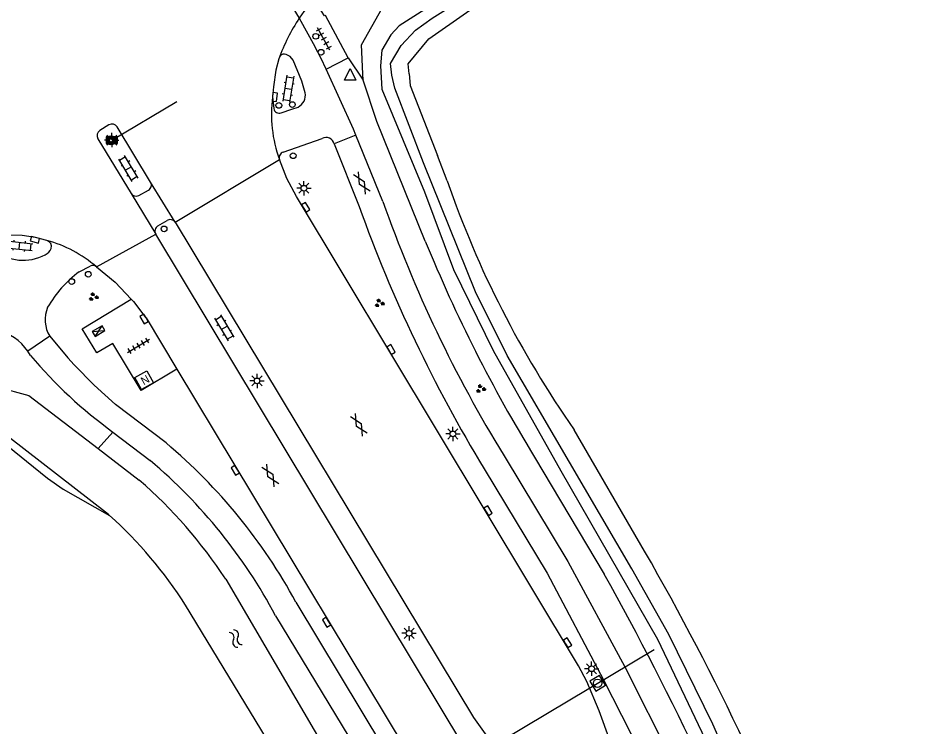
# Model space of a CAD drawing. Extents: x 133000 to 136000, y 400500 to 403500.
# Drawn here: x 133580.3 to 133659.3, y 400942.9 to 401004.9 of the extents above; entities that cross this region are included whole.
import ezdxf

# ---------------------------------------------------------------- set-up
doc = ezdxf.new("R2010")
doc.units = 0
for name, color, linetype in [('gg-afsc-erfafscheiding', 7, 'Continuous'), ('gg-knt-verharding', 7, 'Continuous'), ('gg-knt-verharding nz', 7, 'Continuous'), ('gg-kntw-bovenkant insteek waterloop', 7, 'Continuous'), ('gg-kntw-waterlijn', 7, 'Continuous'), ('gg-kwrk-duiker nz buis', 7, 'Continuous'), ('gt-grn-groengrens', 7, 'Continuous'), ('gt-grn-weggrens', 7, 'Continuous'), ('gt-knt-lijn portaal', 7, 'Continuous'), ('gt-symb-drukknoppaal', 7, 'Continuous'), ('gt-symb-gesloten verharding', 7, 'Continuous'), ('gt-symb-groenvak', 7, 'Continuous'), ('gt-symb-klinker verharding', 7, 'Continuous'), ('gt-symb-kolk', 7, 'Continuous'), ('gt-symb-lichtmast', 7, 'Continuous'), ('gt-symb-nortonput', 7, 'Continuous'), ('gt-symb-portaalmast', 7, 'Continuous'), ('gt-symb-rioolschacht', 7, 'Continuous'), ('gt-symb-tegel verharding', 7, 'Continuous'), ('gt-symb-verkeersregelinstallatiekast', 7, 'Continuous'), ('gt-symb-verkeersregelinstallatiepaal', 7, 'Continuous'), ('gt-symb-waterafsluiter', 7, 'Continuous'), ('gt-symb-watersymbool', 7, 'Continuous'), ('gt-symb-wegwijzer', 7, 'Continuous')]:
    doc.layers.add(name, color=color, linetype=linetype)

# ---------------------------------------------------------------- blocks, each defined once
blk = doc.blocks.new('gt0-LMAST')
at = {"layer": 'gt-symb-lichtmast'}
for p, q in [((-0.182, 0.173), (-0.447, 0.438)), ((-0.005, 0.246), (-0.005, 0.621)), ((0.172, 0.173), (0.437, 0.438)), ((-0.255, -0.004), (-0.63, -0.004)), ((-0.182, -0.181), (-0.447, -0.446)), ((-0.005, -0.254), (-0.005, -0.629)), ((0.437, -0.446), (0.172, -0.181)), ((0.245, -0.004), (0.62, -0.004))]:
    blk.add_line(p, q, dxfattribs=at)
blk.add_circle((-0.005, -0.004), 0.25, dxfattribs=at)
blk = doc.blocks.new('gt0-VIPAAL')
at = {"layer": 'gt-symb-verkeersregelinstallatiepaal'}
blk.add_circle((0, 0), 0.25, dxfattribs=at)
blk = doc.blocks.new('gt0-DPAAL')
at = {"layer": 'gt-symb-drukknoppaal'}
blk.add_circle((0, 0), 0.25, dxfattribs=at)
blk = doc.blocks.new('gt0-KOLK')
at = {"layer": 'gt-symb-kolk'}
blk.add_lwpolyline([(0, 0), (0.375, 0), (0.375, 0.4), (-0.375, 0.4), (-0.375, 0), (0, 0)], dxfattribs=at)
blk = doc.blocks.new('gt0-KL1')
at = {"layer": 'gt-symb-klinker verharding'}
for p, q in [((-1.15, 0.3), (1.15, 0.3)), ((-1, -0.3), (-1, 0.3)), ((-0.5, 0.3), (-0.5, 0.45)), ((0, -0.3), (0, 0.3)), ((0.5, 0.3), (0.5, 0.45)), ((1, -0.3), (1, 0.3)), ((-1.15, -0.3), (1.15, -0.3)), ((-0.5, -0.45), (-0.5, -0.3)), ((0.5, -0.45), (0.5, -0.3))]:
    blk.add_line(p, q, dxfattribs=at)
blk = doc.blocks.new('gt0-TEG1')
at = {"layer": 'gt-symb-tegel verharding'}
for p, q in [((-1.125, 0), (1.125, 0)), ((-0.9, -0.25), (-0.9, 0.25)), ((-0.45, -0.25), (-0.45, 0.25)), ((0, -0.25), (0, 0.25)), ((0.45, -0.25), (0.45, 0.25)), ((0.9, -0.25), (0.9, 0.25))]:
    blk.add_line(p, q, dxfattribs=at)
blk = doc.blocks.new('gt0-PORTM')
at = {"layer": 'gt-symb-portaalmast'}
for radius in [0.4, 0.33, 0.27, 0.21, 0.15]:
    blk.add_circle((0, 0), radius, dxfattribs=at)
blk = doc.blocks.new('gt0-WW')
at = {"layer": 'gt-symb-wegwijzer'}
blk.add_lwpolyline([(-0.5, 0.295), (-0.5, -0.295), (0.5, -0.295), (0.5, 0.295), (-0.5, 0.295)], dxfattribs=at)
blk.add_lwpolyline([(-0.418, -0.212), (0.417, -0.212), (0.417, 0.212), (-0.418, 0.212)], close=True, dxfattribs=at)
blk = doc.blocks.new('gt0-GRVAK')
at = {"layer": 'gt-symb-groenvak'}
for p, q in [((-0.11, 0.189), (-0.228, 0.24)), ((-0.182, 0.153), (0.088, 0.153)), ((-0.091, 0.211), (-0.156, 0.322)), ((-0.047, 0.214), (-0.047, 0.393)), ((-0.004, 0.211), (0.061, 0.322)), ((0.015, 0.189), (0.133, 0.24)), ((0.262, -0.052), (0.197, 0.059)), ((0.305, -0.049), (0.305, 0.13)), ((0.349, -0.052), (0.414, 0.059)), ((-0.245, -0.228), (-0.363, -0.177)), ((-0.318, -0.264), (-0.047, -0.264)), ((-0.226, -0.206), (-0.291, -0.095)), ((-0.183, -0.203), (-0.183, -0.024)), ((-0.139, -0.206), (-0.074, -0.095)), ((-0.12, -0.228), (-0.002, -0.177)), ((0.243, -0.074), (0.125, -0.023)), ((0.17, -0.11), (0.441, -0.11)), ((0.368, -0.074), (0.486, -0.023))]:
    blk.add_line(p, q, dxfattribs=at)
blk = doc.blocks.new('gt0-VRIKST')
at = {"layer": 'gt-symb-verkeersregelinstallatiekast'}
for p, q in [((-0.501, -0.249), (0.501, 0.249)), ((-0.501, 0.249), (0.501, -0.249))]:
    blk.add_line(p, q, dxfattribs=at)
blk.add_lwpolyline([(0.501, 0.249), (-0.501, 0.249), (-0.501, -0.249), (0.501, -0.249)], close=True, dxfattribs=at)
blk = doc.blocks.new('gt0-NPUT')
at = {"layer": 'gt-symb-nortonput'}
blk.add_lwpolyline([(-0.566, -0.608), (-0.566, 0.592), (0.634, 0.592), (0.634, -0.608)], close=True, dxfattribs=at)
blk.add_text('N', height=0.7, dxfattribs=at).set_placement((-0.221, -0.381))
blk = doc.blocks.new('gt0-WA')
at = {"layer": 'gt-symb-watersymbool'}
for centre, start, end in [((-0.323, 0.022), 28.07249, 151.92751), ((0.427, 0.422), 208.07248, 331.92751), ((-0.323, -0.428), 28.07249, 151.92751), ((0.427, -0.028), 208.07248, 331.92751)]:
    blk.add_arc(centre, 0.425, start, end, dxfattribs=at)
blk = doc.blocks.new('gt0-GESVH1')
at = {"layer": 'gt-symb-gesloten verharding'}
for p, q in [((-0.992, -0.261), (0.008, 0.239)), ((0.008, -0.261), (-0.992, 0.239)), ((0.008, 0.239), (1.008, -0.261)), ((1.008, 0.239), (0.008, -0.261))]:
    blk.add_line(p, q, dxfattribs=at)
blk = doc.blocks.new('gt0-WAFSL')
at = {"layer": 'gt-symb-waterafsluiter'}
for p, q in [((-0.5, -0.333), (0, 0.667)), ((0, 0.667), (0.5, -0.333)), ((0.5, -0.333), (-0.5, -0.333))]:
    blk.add_line(p, q, dxfattribs=at)
blk = doc.blocks.new('gt0-RS')
at = {"layer": 'gt-symb-rioolschacht'}
blk.add_lwpolyline([(-0.5, -0.5), (0.5, -0.5), (0.5, 0.5), (-0.5, 0.5)], close=True, dxfattribs=at)
blk.add_circle((0, 0), 0.375, dxfattribs=at)

msp = doc.modelspace()

# ---------------------------------------------------------------- linework, layer by layer
at = {"layer": 'gg-afsc-erfafscheiding'}
msp.add_lwpolyline([(133429.627, 400949.865), (133442.716, 400946.867), (133458.33, 400944.553), (133473.772, 400943.808), (133489.111, 400944.33), (133504.61, 400946.174), (133524.569, 400949.018), (133536.245, 400951.941), (133555.852, 400958.891), (133578.738, 400967.971), (133582.861, 400964.612), (133584.248, 400963.669), (133588.295, 400961.359)], dxfattribs=at)
at = {"layer": 'gg-knt-verharding'}
for p, q in [((133604.882, 401004.877), (133606.25, 401002.402)), ((133603.217, 401001.565), (133603.102, 401001.303)), ((133607.223, 401000.406), (133609.169, 401001.412)), ((133602.539, 400997.986), (133602.652, 400996.955)), ((133588.238, 400995.529), (133587.436, 400995.054)), ((133591.883, 400990.527), (133588.965, 400995.361)), ((133587.28, 400994.311), (133590.173, 400989.538)), ((133603.473, 400993.158), (133606.884, 400994.336)), ((133612.188, 400988.84), (133609.842, 400994.646)), ((133607.933, 400993.875), (133610.119, 400988.402)), ((133594.022, 400987.01), (133591.883, 400990.527)), ((133590.173, 400989.538), (133592.326, 400985.96)), ((133590.842, 400989.359), (133591.696, 400989.831)), ((133592.514, 400986.687), (133593.341, 400987.178)), ((133622.394, 400936.022), (133592.326, 400985.96)), ((133585.633, 400982.685), (133586.604, 400983.173)), ((133583.06, 400977.033), (133584.638, 400975.161)), ((133581.38, 400975.36), (133581.154, 400975.727)), ((133584.638, 400975.161), (133585.193, 400974.537)), ((133594.178, 400974.168), (133616.436, 400937.165)), ((133588.594, 400968.657), (133591.851, 400966.157)), ((133604.587, 400953.771), (133615.624, 400935.444)), ((133602.814, 400952.587), (133614.646, 400933.075))]:
    msp.add_line(p, q, dxfattribs=at)
for points in [[(133609.169, 401001.412), (133607.179, 401005.103), (133607.074, 401005.081), (133606.552, 401005.903)], [(133607.223, 401000.406), (133606.79, 401001.35), (133606.25, 401002.402)], [(133605.397, 400998.34), (133605.108, 400999.345), (133604.358, 401001.194), (133604.086, 401001.515), (133603.739, 401001.684)], [(133603.102, 401001.303), (133602.843, 401000.327), (133602.636, 400998.86), (133602.539, 400997.986)], [(133609.842, 400994.646), (133609.635, 400995.16), (133607.223, 401000.406)], [(133603.294, 400996.59), (133604.224, 400996.92), (133604.772, 400997.093)], [(133643.238, 400920.543), (133642.873, 400920.331), (133636.597, 400931.123), (133635.215, 400933.677), (133633.976, 400936.304), (133631.096, 400944.275), (133630.018, 400946.839), (133629.31, 400948.2), (133604.634, 400989.261), (133603.808, 400990.837), (133603.152, 400992.491), (133603.149, 400992.499)], [(133594.022, 400987.01), (133620.102, 400943.681), (133621.853, 400941.232)], [(133582.822, 400985.414), (133581.818, 400985.676), (133580.66, 400985.86), (133578.281, 400985.886), (133578.197, 400985.87)], [(133587.144, 400983.115), (133588.781, 400981.783), (133590.193, 400980.298)], [(133594.178, 400974.168), (133591.044, 400972.291), (133588.57, 400976.398), (133587.173, 400975.575), (133585.888, 400977.695), (133590.193, 400980.298)], [(133590.193, 400980.298), (133590.39, 400980.09), (133591.473, 400978.665)], [(133591.473, 400978.665), (133591.481, 400978.652), (133594.178, 400974.168)], [(133593.234, 400967.706), (133588.822, 400971.077), (133586.954, 400972.751), (133585.193, 400974.537)], [(133622.79, 400966.584), (133628.373, 400957.346), (133633.342, 400948.107), (133637.408, 400940.058), (133642.118, 400929.726), (133645.163, 400921.96)], [(133621.061, 400965.43), (133626.564, 400956.32), (133631.485, 400946.992), (133635.443, 400939.199), (133640.107, 400929.009), (133643.445, 400920.663), (133643.238, 400920.543)]]:
    msp.add_lwpolyline(points, dxfattribs=at)
for centre, radius, start, end in [((133618.529, 400995.84), 16.368, 136.91089, 146.48973), ((133618.494, 400995.867), 16.324, 146.50012, 160.54947), ((133603.562, 401001.254), 0.465, 67.65587, 138.02856), ((133604.297, 400998.111), 1.124, 295.01647, 11.74321), ((133614.053, 400996.489), 11.611, 172.59066, 200.0966), ((133603.114, 400997.021), 0.467, 188.08266, 292.67778), ((133588.515, 400995.071), 0.536, 32.83907, 121.13717), ((133587.737, 400994.603), 0.542, 123.71307, 212.5718), ((133607.234, 400993.708), 0.719, 13.45108, 119.10119), ((133603.632, 400992.671), 0.512, 108.04994, 199.58761), ((133591.455, 400990.269), 0.5, 298.80536, 31.11672), ((133590.601, 400989.798), 0.501, 211.24704, 298.79419), ((133721.638, 401027.325), 116.018, 199.37277, 211.5703), ((133728.656, 401030.771), 125.882, 199.66875, 211.26994), ((133593.596, 400986.747), 0.5, 31.64774, 120.63639), ((133592.778, 400986.231), 0.527, 120.10338, 210.89883), ((133582.658, 400984.883), 0.556, 342.87606, 72.79721), ((133580.731, 400987.799), 4.11, 231.28374, 298.03141), ((133582.179, 400985.163), 1.103, 295.95387, 336.28438), ((133592.07, 400974.214), 10.639, 127.2324, 149.76831), ((133585.522, 400978.485), 2.858, 157.67321, 210.53011), ((133577.43, 400973.173), 4.515, 34.43853, 118.11645), ((133612.682, 401001.815), 40.984, 220.20285, 234.0028), ((133562.317, 400930.926), 48.048, 28.38977, 49.95041), ((133562.318, 400931.085), 45.85, 27.96746, 49.90099)]:
    msp.add_arc(centre, radius, start, end, dxfattribs=at)
at = {"layer": 'gg-knt-verharding nz'}
for centre, radius, start, end in [((133579.943, 400974.79), 11.007, 49.14108, 74.83925), ((133586.829, 400982.727), 0.499, 50.9258, 116.81322)]:
    msp.add_arc(centre, radius, start, end, dxfattribs=at)
at = {"layer": 'gg-kntw-bovenkant insteek waterloop'}
for p, q in [((133610.48, 400999.43), (133610.454, 401000)), ((133617.826, 400990.628), (133616.964, 400992.854)), ((133635.078, 400958.233), (133628.929, 400968.862)), ((133587.308, 400967.207), (133590.884, 400964.463)), ((133625.459, 400966.466), (133631.548, 400956.23)), ((133598.45, 400955.778), (133611.212, 400934.007)), ((133607.901, 400932.143), (133594.931, 400953.522))]:
    msp.add_line(p, q, dxfattribs=at)
for points in [[(133610.454, 401000), (133610.337, 401002.541), (133612.12, 401005.733), (133633.867, 401018.749), (133649.14, 401028.319), (133655.678, 401032.336), (133664.278, 401037.462), (133672.933, 401042.494), (133680.547, 401046.788), (133688.225, 401050.968), (133697.299, 401055.725), (133706.431, 401060.369), (133707.975, 401061.051), (133711.698, 401062.516), (133713.355, 401059.623)], [(133614.492, 401000), (133614.416, 401000.87), (133616.202, 401003.055), (133623.098, 401007.897), (133635.496, 401015.813), (133639.764, 401018.462), (133648.605, 401023.858), (133657.482, 401029.194), (133666.111, 401034.245), (133673.135, 401038.207)], [(133614.492, 401000), (133614.583, 400998.968), (133616.964, 400992.854)], [(133588.295, 400961.359), (133588.192, 400961.451), (133579.361, 400968.304), (133578.58, 400968.502), (133571.943, 400966.804), (133565.509, 400965.052), (133559.077, 400962.776), (133539.963, 400956.262), (133519.917, 400950.936), (133499.845, 400947.79), (133478.527, 400946.659), (133457.666, 400947.654), (133436.605, 400950.84), (133415.789, 400956.042), (133374.475, 400971.814), (133356.681, 400978.499), (133345.411, 400982.38), (133332.882, 400986.151), (133319.753, 400989.747), (133303.119, 400993.146), (133285.229, 400995.886), (133269.888, 400998.388), (133256.467, 400999.27)], [(133615.901, 400985.371), (133611.658, 400995.839), (133610.48, 400999.43)], [(133557.489, 400966.438), (133558.125, 400966.65), (133564.041, 400968.841), (133570.425, 400970.617), (133578.451, 400972.606), (133581.25, 400971.856), (133587.308, 400967.207)]]:
    msp.add_lwpolyline(points, dxfattribs=at)
for centre, radius, start, end in [((133700.133, 401018.899), 87.027, 198.95642, 215.09652), ((133734.998, 401033.715), 128.535, 202.09345, 211.54709), ((133563.396, 400932.879), 41.871, 33.15504, 48.96693), ((133563.193, 400933.376), 37.593, 32.40607, 48.10662), ((133441.615, 400846.777), 223.272, 20.24389, 29.94663), ((133406.374, 400830.346), 257.973, 20.93223, 29.20755)]:
    msp.add_arc(centre, radius, start, end, dxfattribs=at)
at = {"layer": 'gg-kntw-waterlijn'}
for points in [[(133669.178, 400882.869), (133660.123, 400899.947), (133656.816, 400906.406), (133654.565, 400911.047), (133649.821, 400922.128), (133646.196, 400931.346), (133641.046, 400943.094), (133637.201, 400950.933), (133633.964, 400956.689), (133623.055, 400975.355), (133620.284, 400980.931), (133615.747, 400992.22), (133613.24, 400998.75), (133612.979, 400999.877), (133612.868, 401000.913), (133613.799, 401002.477), (133615.033, 401003.815), (133616.515, 401004.871), (133629.865, 401013.235), (133660.984, 401032.244), (133689.357, 401048.211), (133697.388, 401052.73), (133707.228, 401057.72)], [(133702.993, 401056.634), (133698.278, 401054.31), (133668.171, 401037.676), (133654.636, 401029.646), (133630.286, 401014.659), (133622.458, 401009.841), (133613.627, 401004.192), (133612.898, 401003.401), (133612.106, 401002.064), (133611.983, 401000.708), (133612.106, 400998.666), (133615.821, 400989.679), (133618.371, 400982.882), (133621.825, 400975.783), (133627.738, 400965.269), (133636.197, 400950.536), (133640.667, 400941.171), (133648.674, 400922.773), (133653.89, 400910.159), (133663.361, 400891.527), (133670.025, 400879.232)]]:
    msp.add_lwpolyline(points, dxfattribs=at)
at = {"layer": 'gg-kwrk-duiker nz buis'}
msp.add_lwpolyline([(133609.989, 400934.441), (133615.169, 400937.241), (133635.906, 400949.645)], dxfattribs=at)
at = {"layer": 'gt-grn-groengrens'}
for p, q in [((133609.169, 401001.412), (133610.48, 400999.43)), ((133587.308, 400967.207), (133588.594, 400968.657))]:
    msp.add_line(p, q, dxfattribs=at)
at = {"layer": 'gt-grn-weggrens'}
for p, q in [((133600.26, 401012.404), (133604.882, 401004.877)), ((133609.842, 400994.646), (133607.933, 400993.875)), ((133594.022, 400987.01), (133603.149, 400992.499)), ((133587.144, 400983.115), (133592.326, 400985.96)), ((133583.06, 400977.033), (133581.154, 400975.727))]:
    msp.add_line(p, q, dxfattribs=at)
at = {"layer": 'gt-knt-lijn portaal'}
msp.add_line((133588.495, 400994.203), (133594.168, 400997.577), dxfattribs=at)

# ---------------------------------------------------------------- block references
at = {"layer": 'gt-symb-drukknoppaal'}
for p in [(133606.786, 401001.888), (133604.275, 400997.309), (133584.985, 400981.823)]:
    msp.add_blockref('gt0-DPAAL', p, dxfattribs=at)
at = {"layer": 'gt-symb-gesloten verharding'}
for p, rotation in [((133610.355, 400990.465), -58.996932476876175), ((133610.086, 400969.269), 121.05216071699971), ((133602.347, 400964.846), 121.05216071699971)]:
    msp.add_blockref('gt0-GESVH1', p, dxfattribs=dict(at, rotation=rotation))
at = {"layer": 'gt-symb-groenvak'}
for p in [(133586.883, 400980.488), (133611.882, 400979.932), (133620.738, 400972.442)]:
    msp.add_blockref('gt0-GRVAK', p, dxfattribs=at)
at = {"layer": 'gt-symb-klinker verharding'}
for p, rotation in [((133603.918, 400998.703), -99.20796905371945), ((133589.946, 400991.712), 121.05216071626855), ((133580.409, 400984.959), -6.143995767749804), ((133598.318, 400977.782), -58.99693247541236)]:
    msp.add_blockref('gt0-KL1', p, dxfattribs=dict(at, rotation=rotation))
at = {"layer": 'gt-symb-kolk'}
for p, rotation in [((133602.539, 400997.986), -96.31488442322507), ((133605.279, 400988.223), -58.12218352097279), ((133581.818, 400985.676), 165.35262473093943), ((133591.481, 400978.652), 121.05216071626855), ((133612.728, 400975.777), -59.075540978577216), ((133599.451, 400965.415), 121.00306752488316), ((133621.223, 400961.677), -58.94783928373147), ((133607.44, 400952.128), 121.00306752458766), ((133628.168, 400950.125), -58.996932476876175)]:
    msp.add_blockref('gt0-KOLK', p, dxfattribs=dict(at, rotation=rotation))
at = {"layer": 'gt-symb-lichtmast'}
for p in [(133588.495, 400994.203), (133605.291, 400989.99), (133601.192, 400973.14), (133618.317, 400968.496), (133614.488, 400951.054), (133630.446, 400947.955)]:
    msp.add_blockref('gt0-LMAST', p, dxfattribs=at)
at = {"layer": 'gt-symb-nortonput', "rotation": 29.588607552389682}
msp.add_blockref('gt0-NPUT', (133591.285, 400973.183), dxfattribs=at)
at = {"layer": 'gt-symb-portaalmast'}
msp.add_blockref('gt0-PORTM', (133588.418, 400994.174), dxfattribs=at)
at = {"layer": 'gt-symb-rioolschacht', "rotation": 30.79671391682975}
msp.add_blockref('gt0-RS', (133630.972, 400946.678), dxfattribs=at)
at = {"layer": 'gt-symb-tegel verharding'}
for p, rotation in [((133607.016, 401003.055), 119.28282857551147), ((133590.832, 400976.207), 31.13079914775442)]:
    msp.add_blockref('gt0-TEG1', p, dxfattribs=dict(at, rotation=rotation))
at = {"layer": 'gt-symb-verkeersregelinstallatiekast', "rotation": 30.523645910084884}
msp.add_blockref('gt0-VRIKST', (133587.336, 400977.491), dxfattribs=at)
at = {"layer": 'gt-symb-verkeersregelinstallatiepaal'}
for p in [(133606.322, 401003.278), (133603.093, 400997.236), (133604.349, 400992.834), (133593.063, 400986.434), (133586.433, 400982.461)]:
    msp.add_blockref('gt0-VIPAAL', p, dxfattribs=at)
at = {"layer": 'gt-symb-waterafsluiter'}
msp.add_blockref('gt0-WAFSL', (133609.325, 400999.785), dxfattribs=at)
at = {"layer": 'gt-symb-watersymbool', "rotation": -59.12470831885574}
msp.add_blockref('gt0-WA', (133599.294, 400950.633), dxfattribs=at)
at = {"layer": 'gt-symb-wegwijzer'}
msp.add_blockref('gt0-WW', (133588.495, 400994.203), dxfattribs=at)

doc.saveas('drawing.dxf')
